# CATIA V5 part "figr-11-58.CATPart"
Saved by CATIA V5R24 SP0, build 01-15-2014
Part number: Part1
Bounding box of the stored display mesh (mm): x -59.829 to 59.829, y -71.429 to 72.174, z -61 to 76
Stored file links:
  D:\KAVITA\CATIA V5-6R2014 Project_ Kavita\CATIA V5-6R2014_partfiles\Partfiles\c11_catia_v5-6r2014_prt\figr-11-58.CATPart
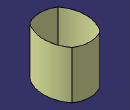
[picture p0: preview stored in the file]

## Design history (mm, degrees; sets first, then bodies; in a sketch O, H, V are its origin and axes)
Set1
  Extrude1: Element1 Sketch1, Lim1 76, Lim2 61, Direction xy-plane
Body1 (main body)
  Sketch1 on xy-plane, origin (0, 0, 0), H (0, 1, 0), V (-1, 0, 0)
    arc A1 centre (0, -40) radius 100 from (-60, 40) to (60, 40) cw
    point P2 (0, 60)
    point P3 (-60, 40)
    point P4 (60, 40)
    axis line L1 (-90, 0) -> (80, 0)
    point P6 (80, 0)
    point P7 (60, -40)
    point P8 (-60, -40)
    arc A2 centre (0, 40) radius 100 from (-60, -40) to (60, -40) ccw
    arc A3 centre (4.2857, 0) radius 75.7143 from (-60, 40) to (-60, -40) ccw
    arc A4 centre (0.3727, 0) radius 71.8012 from (60, -40) to (60, 40) ccw
    coincidence: A1 P2, P2 V, A3 P6
    horizontal: L1 H
    symmetry: P4 P7 L1, P3 P8 L1, A1 A2 L1
    tangency: A4 A3
  Sketch2 on xy-plane, origin (0, 0, 0), H (1, 0, 0), V (0, 1, 0)
    spline S1 through (80, 90) (60, 60) (70, 0) (50, -50) (50, -80)
    point P1 (70, 0)
    coincidence: P1 H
